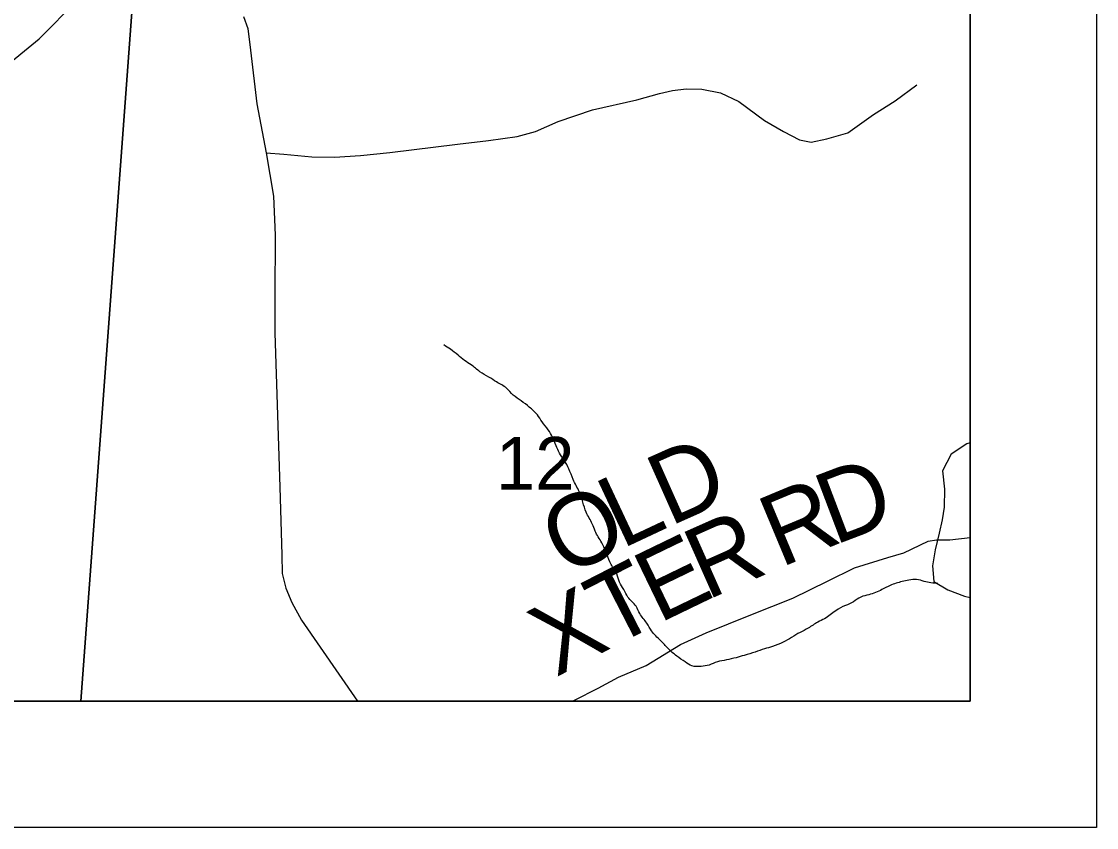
# Model space of a CAD drawing. Extents: x -13.7 to 34, y 0 to 32.3.
# Drawn here: x 29.565 to 30.417, y 14 to 14.638 of the extents above; entities that cross this region are included whole.
import ezdxf

# ---------------------------------------------------------------- set-up
doc = ezdxf.new("R2010")
doc.units = 0
for name, color, linetype in [('GM_X_Corporation', 7, 'Continuous'), ('GM_X_County_Road', 7, 'Continuous'), ('GM_X_Major_River', 7, 'Continuous'), ('GM_X_Minor_River', 7, 'Continuous'), ('GM_X_Section_Text', 7, 'Continuous'), ('GM_X_Township_Road', 7, 'Continuous'), ('GM_X_Township_Road_Text', 7, 'Continuous'), ('SH_Data', 7, 'Continuous')]:
    doc.layers.add(name, color=color, linetype=linetype)

msp = doc.modelspace()

# ---------------------------------------------------------------- linework, layer by layer
at = {"layer": 'GM_X_Corporation'}
msp.add_lwpolyline([(25.54914, 14.1), (30.31667, 14.1), (30.31667, 20.877), (30.27752, 20.87955), (29.95979, 20.9), (26.00265, 20.9)], dxfattribs=at)
for points in [[(25.54914, 14.1), (30.31667, 14.1), (30.31667, 14.73543), (29.70192, 14.77554), (28.65533, 14.83542), (27.68856, 14.89624), (26.84697, 14.93989), (26.25808, 14.9774), (25.61744, 15.0182)], [(28.60732, 14.1), (29.61218, 14.1), (29.66245, 14.77744), (28.66151, 14.83982)], [(29.61218, 14.1), (30.31667, 14.1), (30.31667, 14.73577), (29.66245, 14.77744)]]:
    msp.add_lwpolyline(points, close=True, dxfattribs=at)
at = {"layer": 'GM_X_County_Road'}
for points in [[(29.54869, 14.59928), (29.57928, 14.62426), (29.60962, 14.65485)], [(29.74106, 14.642), (29.74457, 14.63244), (29.74667, 14.61539), (29.75157, 14.5729), (29.75904, 14.53415), (29.76487, 14.49983), (29.76628, 14.46901), (29.76581, 14.42045), (29.76581, 14.39151), (29.76977, 14.26941), (29.77141, 14.21594), (29.77161, 14.20099), (29.77468, 14.18956), (29.77935, 14.17812), (29.78705, 14.16412), (29.83126, 14.1)]]:
    msp.add_lwpolyline(points, dxfattribs=at)
at = {"layer": 'GM_X_Major_River'}
msp.add_lwpolyline([(30.31667, 14.30457), (30.31397, 14.3036), (30.3015, 14.29558), (30.29474, 14.28227), (30.29632, 14.26787), (30.29601, 14.25346), (30.29454, 14.24359), (30.29193, 14.23296), (30.28896, 14.21967), (30.28674, 14.20715), (30.28793, 14.19464), (30.29895, 14.18824), (30.31223, 14.18299), (30.31667, 14.18218)], dxfattribs=at)
at = {"layer": 'GM_X_Minor_River'}
msp.add_spline([(30.29109, 14.19312), (30.28016, 14.19482), (30.2741, 14.1964), (30.26803, 14.1957), (30.2627, 14.19461), (30.25319, 14.19167), (30.2467, 14.18832), (30.23642, 14.18424), (30.22995, 14.18241), (30.22422, 14.17867), (30.21774, 14.1757), (30.21011, 14.1716), (30.20132, 14.16523), (30.19598, 14.16263), (30.18835, 14.15777), (30.18186, 14.15442), (30.1685, 14.14658), (30.16012, 14.14325), (30.15366, 14.14141), (30.14642, 14.13883), (30.13767, 14.13626), (30.1312, 14.13443), (30.12359, 14.13261), (30.11637, 14.13116), (30.1099, 14.12857), (30.10343, 14.12749), (30.09623, 14.12794), (30.09095, 14.13103), (30.08417, 14.13566), (30.0774, 14.1418), (30.0714, 14.14793), (30.06427, 14.1556), (30.06054, 14.16171), (30.05492, 14.16936), (30.05195, 14.17508), (30.04557, 14.18236), (30.04222, 14.18847), (30.03886, 14.19419), (30.03665, 14.20067), (30.03218, 14.20831), (30.02885, 14.21631), (30.02477, 14.22546), (30.01955, 14.23463), (30.01733, 14.24034), (30.01249, 14.2495), (30.00992, 14.2575), (30.00697, 14.26588), (30.00214, 14.27542), (29.99881, 14.28381), (29.99508, 14.29068), (29.99135, 14.29641), (29.98875, 14.30213), (29.98579, 14.30899), (29.98243, 14.31472), (29.97757, 14.32122), (29.97383, 14.32657), (29.96744, 14.33272), (29.96104, 14.33771), (29.95464, 14.34233), (29.94939, 14.3477), (29.94147, 14.35272), (29.93544, 14.35657), (29.92827, 14.36082), (29.9215, 14.3662), (29.91622, 14.36967), (29.91096, 14.3739), (29.90493, 14.37852), (29.89966, 14.38199)], degree=3, dxfattribs=at)
at = {"layer": 'GM_X_Township_Road'}
for points in [[(29.75904, 14.53415), (29.77289, 14.53296), (29.79523, 14.53089), (29.81316, 14.53062), (29.83369, 14.53192), (29.85707, 14.53426), (29.91059, 14.54102), (29.93502, 14.54388), (29.95788, 14.54699), (29.97243, 14.55089), (29.99035, 14.55895), (30.01737, 14.56804), (30.05271, 14.57609), (30.07064, 14.58103), (30.08077, 14.58337), (30.09168, 14.58466), (30.10415, 14.5844), (30.11896, 14.58155), (30.13351, 14.57479), (30.15378, 14.55972), (30.16884, 14.55089), (30.18141, 14.54438), (30.19067, 14.54257), (30.20314, 14.54518), (30.21976, 14.54985), (30.24003, 14.5644), (30.25718, 14.57531), (30.27433, 14.58778)], [(30.00128, 14.1), (30.0033, 14.10077), (30.02204, 14.11024), (30.03803, 14.11912), (30.06012, 14.12819), (30.08715, 14.14476), (30.10746, 14.15403), (30.14297, 14.16824), (30.17611, 14.18165), (30.20353, 14.19506), (30.22503, 14.20552), (30.25147, 14.2138), (30.26409, 14.21755), (30.28342, 14.22663), (30.28997, 14.22782), (30.30059, 14.22761), (30.31667, 14.22956)]]:
    msp.add_lwpolyline(points, dxfattribs=at)
at = {"layer": 'SH_Data'}
for points in [[(23.41667, 21), (30.41667, 21), (30.41667, 14), (23.41667, 14)], [(23.51667, 20.9), (30.31667, 20.9), (30.31667, 14.1), (23.51667, 14.1)]]:
    msp.add_lwpolyline(points, close=True, dxfattribs=at)

# ---------------------------------------------------------------- texts
at = {"layer": 'GM_X_Section_Text'}
msp.add_text('12', height=0.041856, rotation=0.00001, dxfattribs=at).set_placement((29.94093, 14.2673))
at = {"layer": 'GM_X_Township_Road_Text'}
for s, rotation, p in [('D', 24.02278, (30.07857, 14.23809)), ('D', 20.80631, (30.20881, 14.2232)), ('L', 25.13702, (30.04036, 14.22016)), ('R', 22.68201, (30.16621, 14.20538)), ('O', 26.88272, (29.99618, 14.19776)), ('R', 23.93197, (30.10782, 14.17956)), ('E', 25.79647, (30.07, 14.16128)), ('T', 27.19564, (30.03253, 14.14202)), ('X', 27.88799, (29.9885, 14.11871))]:
    msp.add_text(s, height=0.05682, rotation=rotation, dxfattribs=at).set_placement(p)

doc.saveas('drawing.dxf')
